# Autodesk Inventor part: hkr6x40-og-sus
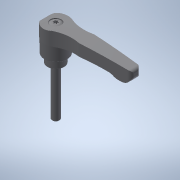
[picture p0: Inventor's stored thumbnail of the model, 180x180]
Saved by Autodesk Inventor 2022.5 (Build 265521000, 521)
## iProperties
Created: 2017-09
Part Number: hkr6x40-og-sus
Material: 一般
Document SubType Name: Modeling
Designer: imaocorp
Density: 1 g/cm^3
Appearance: 既定
Author: imaocorp
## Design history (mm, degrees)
node "hkr6x40-og-sus.x_t1"
node "hkr6x40-og-sus"
node "Base1"
